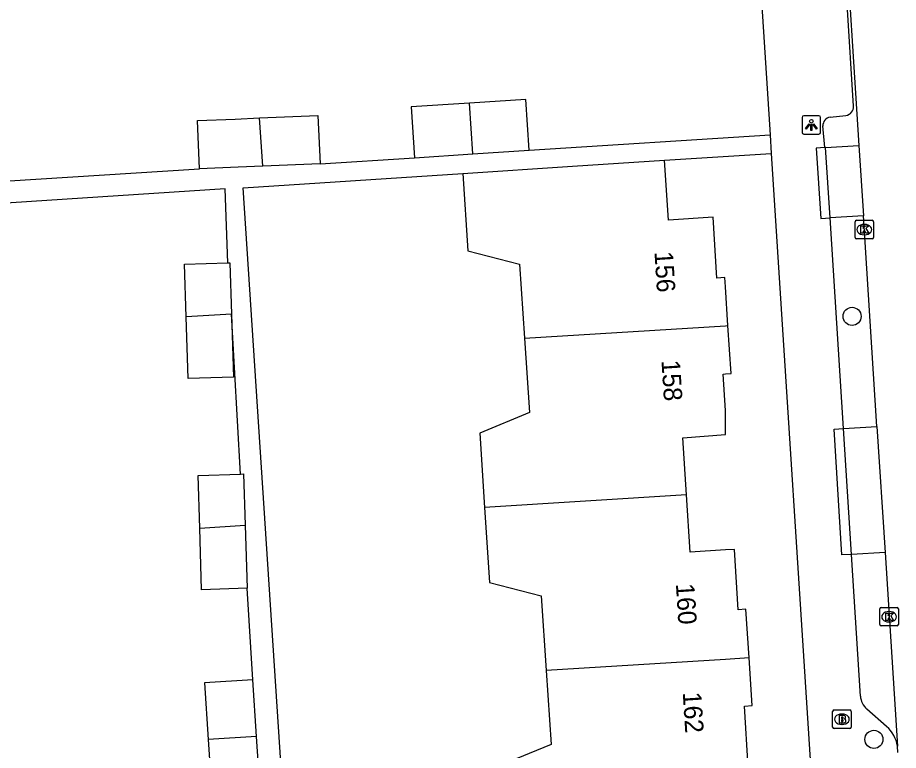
# Model space of a CAD drawing. Extents: x 159628 to 160723, y 388176 to 389416.
# Drawn here: x 160461.73 to 160509.35, y 388427.7 to 388467.32 of the extents above; entities that cross this region are included whole.
import ezdxf

# ---------------------------------------------------------------- set-up
doc = ezdxf.new("R2010")
doc.units = 0
for name, color, linetype in [('IMGEO_Boom', 7, 'Continuous'), ('IMGEO_Brandkraan', 7, 'Continuous'), ('IMGEO_Kolk', 7, 'Continuous'), ('IMGEO_Lichtpunt', 7, 'Continuous'), ('IMGEO_Pand', 7, 'Continuous'), ('IMGEO_Pand_nummerreeks', 7, 'Continuous'), ('IMGEO_Parkeervlak_open', 7, 'Continuous'), ('IMGEO_Rijbaan_lokaal_gesloten', 7, 'Continuous'), ('IMGEO_Voetpad_open', 7, 'Continuous')]:
    doc.layers.add(name, color=color, linetype=linetype)

msp = doc.modelspace()

# ---------------------------------------------------------------- linework, layer by layer
at = {"layer": 'IMGEO_Boom'}
for centre in [(160506.845, 388451.166), (160508.024, 388428.298)]:
    msp.add_circle(centre, 0.489, dxfattribs=at)
at = {"layer": 'IMGEO_Brandkraan'}
for p, q in [((160505.793, 388428.959), (160505.793, 388429.811)), ((160505.868, 388429.885), (160506.72, 388429.885)), ((160506.281, 388429.665), (160506.306, 388429.665)), ((160506.794, 388429.811), (160506.794, 388428.959)), ((160506.72, 388428.885), (160505.868, 388428.885)), ((160506.304, 388429.105), (160506.279, 388429.105))]:
    msp.add_line(p, q, dxfattribs=at)
for points in [[(160505.793, 388428.959), (160505.793, 388429.811)], [(160505.868, 388429.885), (160506.72, 388429.885)], [(160506.794, 388429.811), (160506.794, 388428.959)], [(160506.141, 388429.585), (160506.141, 388429.185), (160506.354, 388429.185)], [(160506.372, 388429.585), (160506.141, 388429.585)], [(160506.32, 388429.504), (160506.266, 388429.504), (160506.266, 388429.428)], [(160506.266, 388429.428), (160506.319, 388429.428)], [(160506.328, 388429.352), (160506.266, 388429.352), (160506.266, 388429.271)], [(160506.266, 388429.271), (160506.328, 388429.271)], [(160506.72, 388428.885), (160505.868, 388428.885)]]:
    msp.add_lwpolyline(points, dxfattribs=at)
for centre, radius, start, end in [((160505.87, 388429.809), 0.0765, 91.552, 178.448), ((160505.87, 388429.809), 0.0765, 91.552, 178.448), ((160506.718, 388429.809), 0.0765, 1.552, 88.448), ((160506.718, 388429.809), 0.0765, 1.552, 88.448), ((160506.321, 388429.466), 0.0379, 267.8285, 90.9355), ((160506.329, 388429.311), 0.0404, 269.8759, 90.5077), ((160506.36, 388429.436), 0.251, 268.6676, 293.5347), ((160506.376, 388429.44), 0.145, 59.4692, 91.5367), ((160506.401, 388429.487), 0.0922, 285.5137, 58.1501), ((160506.406, 388429.295), 0.105, 301.3115, 78.989), ((160505.87, 388428.961), 0.0765, 181.552, 268.448), ((160505.87, 388428.961), 0.0765, 181.552, 268.448), ((160506.718, 388428.961), 0.0765, 271.552, 358.448), ((160506.718, 388428.961), 0.0765, 271.552, 358.448)]:
    msp.add_arc(centre, radius, start, end, dxfattribs=at)
for centre, major_axis, ratio, start_param, end_param in [((160506.28, 388429.385), (-0.387, 0.002), 0.722429, 4.712389, 7.853982), ((160506.305, 388429.385), (-0.39, 0.002), 0.717154, 1.570796, 4.712389)]:
    msp.add_ellipse(centre, major_axis=major_axis, ratio=ratio, start_param=start_param, end_param=end_param, dxfattribs=at)
at = {"layer": 'IMGEO_Kolk'}
for p, q in [((160507.003, 388455.432), (160507.003, 388456.284)), ((160507.078, 388456.358), (160507.93, 388456.358)), ((160508.004, 388456.284), (160508.004, 388455.432)), ((160507.491, 388456.138), (160507.516, 388456.138)), ((160507.93, 388455.358), (160507.078, 388455.358)), ((160507.514, 388455.578), (160507.489, 388455.578)), ((160508.346, 388434.501), (160508.346, 388435.353)), ((160508.421, 388435.427), (160509.273, 388435.427)), ((160509.347, 388435.353), (160509.347, 388434.501)), ((160508.834, 388435.207), (160508.859, 388435.207)), ((160509.273, 388434.427), (160508.421, 388434.427)), ((160508.857, 388434.647), (160508.832, 388434.647))]:
    msp.add_line(p, q, dxfattribs=at)
for points in [[(160507.003, 388455.432), (160507.003, 388456.284)], [(160507.078, 388456.358), (160507.93, 388456.358)], [(160508.004, 388456.284), (160508.004, 388455.432)], [(160507.324, 388456.058), (160507.447, 388456.058), (160507.447, 388455.907), (160507.577, 388456.058), (160507.741, 388456.058), (160507.595, 388455.907), (160507.748, 388455.658), (160507.596, 388455.658), (160507.511, 388455.822), (160507.447, 388455.755), (160507.447, 388455.658), (160507.324, 388455.658), (160507.324, 388456.058)], [(160507.93, 388455.358), (160507.078, 388455.358)], [(160508.346, 388434.501), (160508.346, 388435.353)], [(160508.421, 388435.427), (160509.273, 388435.427)], [(160509.347, 388435.353), (160509.347, 388434.501)], [(160508.667, 388435.127), (160508.79, 388435.127), (160508.79, 388434.976), (160508.92, 388435.127), (160509.084, 388435.127), (160508.938, 388434.976), (160509.091, 388434.727), (160508.939, 388434.727), (160508.854, 388434.891), (160508.79, 388434.824), (160508.79, 388434.727), (160508.667, 388434.727), (160508.667, 388435.127)], [(160509.273, 388434.427), (160508.421, 388434.427)]]:
    msp.add_lwpolyline(points, dxfattribs=at)
for centre, start, end in [((160507.08, 388456.282), 91.552, 178.448), ((160507.08, 388456.282), 91.552, 178.448), ((160507.928, 388456.282), 1.552, 88.448), ((160507.928, 388456.282), 1.552, 88.448), ((160507.08, 388455.434), 181.552, 268.448), ((160507.08, 388455.434), 181.552, 268.448), ((160507.928, 388455.434), 271.552, 358.448), ((160507.928, 388455.434), 271.552, 358.448), ((160508.423, 388435.351), 91.552, 178.448), ((160508.423, 388435.351), 91.552, 178.448), ((160509.271, 388435.351), 1.552, 88.448), ((160509.271, 388435.351), 1.552, 88.448), ((160508.423, 388434.503), 181.552, 268.448), ((160508.423, 388434.503), 181.552, 268.448), ((160509.271, 388434.503), 271.552, 358.448), ((160509.271, 388434.503), 271.552, 358.448)]:
    msp.add_arc(centre, 0.0765, start, end, dxfattribs=at)
for centre, major_axis, ratio, start_param, end_param in [((160507.49, 388455.858), (-0.387, 0.002), 0.722429, 4.712389, 7.853982), ((160507.515, 388455.858), (-0.39, 0.002), 0.717154, 1.570796, 4.712389), ((160508.833, 388434.927), (-0.387, 0.002), 0.722429, 4.712389, 7.853982), ((160508.858, 388434.927), (-0.39, 0.002), 0.717154, 1.570796, 4.712389)]:
    msp.add_ellipse(centre, major_axis=major_axis, ratio=ratio, start_param=start_param, end_param=end_param, dxfattribs=at)
at = {"layer": 'IMGEO_Lichtpunt'}
for p, q in [((160505.044, 388462.012), (160504.236, 388462.012)), ((160505.044, 388462.012), (160504.236, 388462.012)), ((160504.142, 388461.917), (160504.142, 388461.11)), ((160504.142, 388461.917), (160504.142, 388461.11)), ((160505.138, 388461.11), (160505.138, 388461.917)), ((160505.138, 388461.11), (160505.138, 388461.917)), ((160504.236, 388461.016), (160505.044, 388461.016)), ((160504.236, 388461.016), (160505.044, 388461.016))]:
    msp.add_line(p, q, dxfattribs=at)
for points in [[(160504.516, 388461.581), (160504.555, 388461.553), (160504.367, 388461.291), (160504.329, 388461.318), (160504.516, 388461.581)], [(160504.618, 388461.533), (160504.665, 388461.533), (160504.665, 388461.211), (160504.618, 388461.211), (160504.618, 388461.533)], [(160504.728, 388461.553), (160504.766, 388461.58), (160504.953, 388461.318), (160504.914, 388461.29), (160504.728, 388461.553)]]:
    msp.add_lwpolyline(points, dxfattribs=at)
msp.add_circle((160504.641, 388461.715), 0.0994, dxfattribs=at)
for centre, start, end in [((160504.236, 388461.917), 90, 180), ((160504.236, 388461.917), 90, 180), ((160505.044, 388461.917), 0, 90), ((160505.044, 388461.917), 0, 90), ((160504.236, 388461.11), 180, 270), ((160504.236, 388461.11), 180, 270), ((160505.044, 388461.11), 270, 0), ((160505.044, 388461.11), 270, 360)]:
    msp.add_arc(centre, 0.0946, start, end, dxfattribs=at)
at = {"layer": 'IMGEO_Pand'}
for points in [[(160486.164, 388462.698), (160483.01, 388462.492), (160483.19, 388459.738)], [(160489.393, 388460.144), (160489.212, 388462.898), (160486.164, 388462.698)], [(160486.34, 388459.944), (160486.164, 388462.698)], [(160474.814, 388461.89), (160477.968, 388462.024), (160478.08, 388459.412)], [(160471.558, 388459.134), (160471.447, 388461.746), (160473.488, 388461.833), (160474.814, 388461.89)], [(160474.983, 388459.28), (160474.814, 388461.89)], [(160486.34, 388459.944), (160489.393, 388460.144)], [(160483.19, 388459.738), (160486.34, 388459.944)], [(160485.795, 388458.895), (160491.721, 388459.282), (160496.71, 388459.607)], [(160500.133, 388450.668), (160500, 388452.761), (160499.968, 388453.264), (160499.539, 388453.236), (160499.325, 388456.52), (160496.92, 388456.364), (160496.71, 388459.607)], [(160474.983, 388459.28), (160473.657, 388459.223), (160471.558, 388459.134)], [(160478.08, 388459.412), (160474.983, 388459.28)], [(160485.795, 388458.895), (160486.069, 388454.714), (160488.871, 388453.987), (160489.133, 388449.983)], [(160470.84, 388451.134), (160470.752, 388453.984), (160473.102, 388454.057)], [(160473.102, 388454.057), (160473.205, 388454.06), (160473.291, 388451.292)], [(160473.291, 388451.292), (160473.397, 388447.879), (160470.943, 388447.803), (160470.84, 388451.134)], [(160473.291, 388451.292), (160470.84, 388451.134)], [(160489.133, 388449.983), (160500, 388450.66), (160500.133, 388450.668)], [(160497.889, 388441.511), (160497.697, 388444.597), (160500, 388444.772), (160500, 388446.076), (160499.877, 388448.046), (160500, 388448.054), (160500.298, 388448.072), (160500.133, 388450.668)], [(160489.133, 388449.983), (160489.395, 388445.965), (160486.713, 388444.855), (160486.976, 388440.831)], [(160471.575, 388439.722), (160471.487, 388442.571), (160473.77, 388442.642)], [(160473.77, 388442.642), (160473.94, 388442.647), (160474.026, 388439.88)], [(160497.889, 388441.511), (160486.976, 388440.831)], [(160501.276, 388432.703), (160501.104, 388435.331), (160500.687, 388435.305), (160500.485, 388438.565), (160500, 388438.535), (160498.082, 388438.416), (160497.889, 388441.511)], [(160486.976, 388440.831), (160487.242, 388436.773), (160490.043, 388436.059), (160490.307, 388432.019)], [(160471.575, 388439.722), (160474.026, 388439.88)], [(160474.132, 388436.466), (160471.678, 388436.39), (160471.575, 388439.722)], [(160474.026, 388439.88), (160474.132, 388436.466)], [(160490.307, 388432.019), (160490.568, 388428.026), (160487.886, 388426.914), (160488.158, 388422.749), (160499.07, 388423.424), (160498.84, 388426.652), (160500, 388426.735), (160501.229, 388426.821), (160501.029, 388430.098), (160501.444, 388430.129), (160501.276, 388432.703)], [(160501.276, 388432.703), (160500, 388432.623), (160490.307, 388432.019)], [(160474.449, 388431.517), (160471.837, 388431.347), (160472.036, 388428.29)], [(160474.648, 388428.458), (160474.449, 388431.517)], [(160474.648, 388428.458), (160472.036, 388428.29)], [(160472.036, 388428.29), (160472.246, 388425.071), (160474.857, 388425.241)], [(160474.857, 388425.241), (160474.648, 388428.458)]]:
    msp.add_lwpolyline(points, dxfattribs=at)
at = {"layer": 'IMGEO_Parkeervlak_open'}
for points in [[(160505.41, 388460.29), (160507.212, 388460.409)], [(160507.456, 388456.603), (160505.651, 388456.489)], [(160506.376, 388445.1), (160508.187, 388445.216)], [(160508.624, 388438.407), (160506.805, 388438.298)]]:
    msp.add_lwpolyline(points, dxfattribs=at)
at = {"layer": 'IMGEO_Rijbaan_lokaal_gesloten'}
for points in [[(160505.579, 388485.867), (160507.212, 388460.409)], [(160507.212, 388460.409), (160507.456, 388456.603)], [(160508.187, 388445.216), (160507.456, 388456.603)], [(160508.187, 388445.216), (160508.624, 388438.407)], [(160508.624, 388438.407), (160509.296, 388427.933)], [(160509.318, 388427.594), (160509.296, 388427.933)]]:
    msp.add_lwpolyline(points, dxfattribs=at)
at = {"layer": 'IMGEO_Voetpad_open'}
for points in [[(160500.653, 388488.259), (160502.409, 388460.978)], [(160506.926, 388462.536), (160506.233, 388473.579)], [(160505.657, 388461.942), (160506.506, 388462.028)], [(160505.373, 388460.288), (160505.265, 388461.457)], [(160489.393, 388460.144), (160502.409, 388460.978)], [(160502.409, 388460.978), (160502.473, 388459.978)], [(160505.373, 388460.288), (160504.896, 388460.256), (160505.147, 388456.457), (160505.651, 388456.489)], [(160505.41, 388460.29), (160505.373, 388460.288)], [(160505.651, 388456.489), (160505.41, 388460.29)], [(160478.08, 388459.412), (160483.19, 388459.738)], [(160496.71, 388459.607), (160502.473, 388459.978)], [(160502.473, 388459.978), (160504.835, 388423.287)], [(160457.563, 388458.265), (160471.558, 388459.134)], [(160476.311, 388421.541), (160473.914, 388458.116), (160485.795, 388458.895)], [(160473.102, 388454.057), (160472.946, 388458.053), (160442.905, 388456.093)], [(160506.376, 388445.1), (160505.651, 388456.489)], [(160473.77, 388442.642), (160473.291, 388451.292)], [(160506.805, 388438.298), (160506.285, 388438.267), (160505.877, 388445.068), (160506.376, 388445.1)], [(160506.805, 388438.298), (160506.376, 388445.1)], [(160507.296, 388430.636), (160506.805, 388438.298)], [(160474.449, 388431.517), (160474.132, 388436.466)], [(160508.711, 388428.994), (160507.648, 388429.922)]]:
    msp.add_lwpolyline(points, dxfattribs=at)
for centre, radius, start, end in [((160506.43, 388462.519), 0.496, 278.8235, 2.0106), ((160505.748, 388461.467), 0.484, 100.9023, 181.2041), ((160508.334, 388430.704), 1.04, 183.7471, 228.7392), ((160507.532, 388427.652), 1.786, 9.0449, 48.6968)]:
    msp.add_arc(centre, radius, start, end, dxfattribs=at)

# ---------------------------------------------------------------- texts
at = {"layer": 'IMGEO_Pand_nummerreeks'}
for s, rotation, p in [('156', 273.6839, (160496.158, 388454.658)), ('158', 273.6839, (160496.536, 388448.783)), ('160', 273.6249, (160497.317, 388436.702)), ('162', 273.6249, (160497.688, 388430.836))]:
    msp.add_text(s, height=1, rotation=rotation, dxfattribs=at).set_placement(p)

doc.saveas('drawing.dxf')
